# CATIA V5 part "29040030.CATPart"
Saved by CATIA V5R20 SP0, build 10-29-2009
Part number: 29040030
Definition: NONE
Nomenclature: 29040030
Source: Unknown
Description: 29040030
Bounding box of the stored display mesh (mm): x -15 to 44.548, y -34 to 68.548, z -24 to 24
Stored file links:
  C:\Users\Utente\Desktop\IO LAVORO\3D X SITO CF\X SITO\PLASTICA\RF1\29040030.CATPart
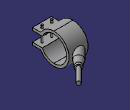
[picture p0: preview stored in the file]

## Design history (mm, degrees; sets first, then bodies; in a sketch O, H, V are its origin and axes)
Body1 "29040030" (main body)
  Solid1: solid without history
